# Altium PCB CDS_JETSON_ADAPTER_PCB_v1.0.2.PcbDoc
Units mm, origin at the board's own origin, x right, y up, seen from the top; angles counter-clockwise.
Board outline 70 x 50 mm, 2 copper layers (Top Layer, Bottom Layer); 70 components, 61 nets, 287 pads, 164 vias.
Unrouted connection lines stored in the file: 53.
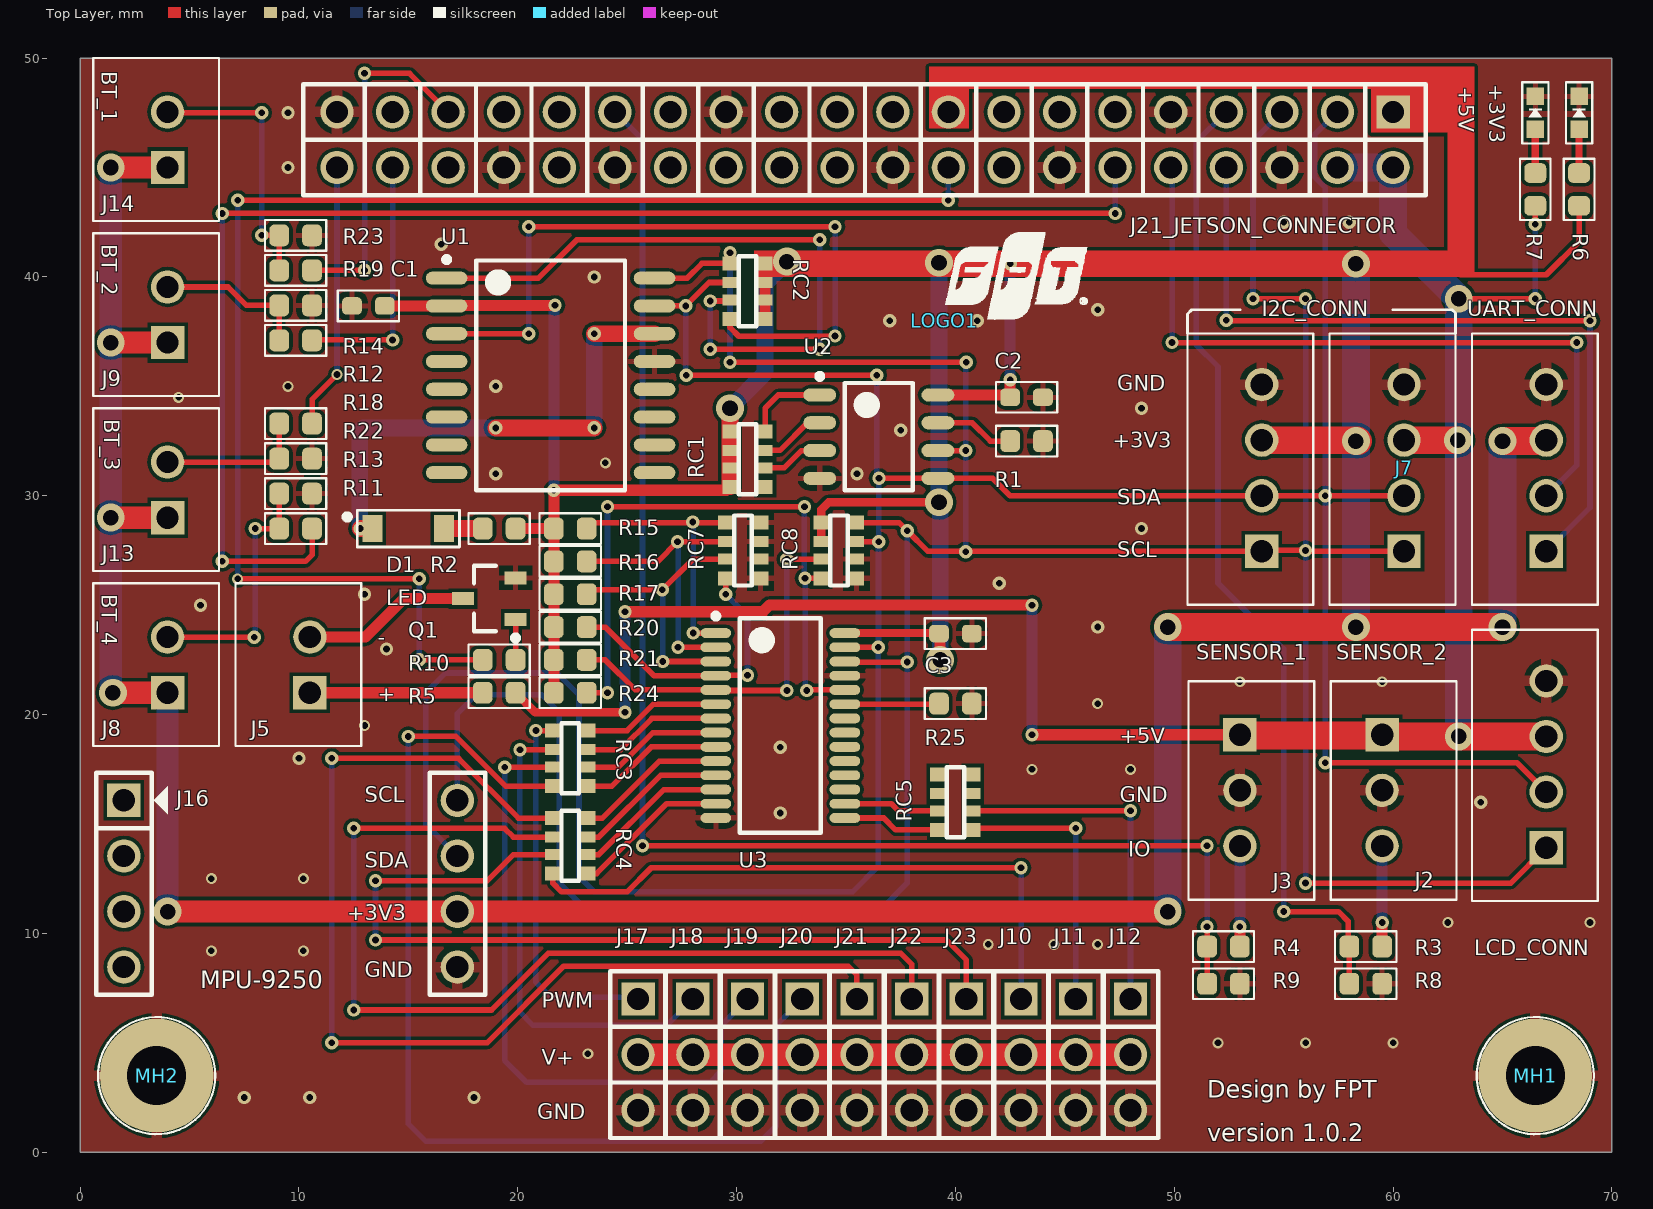
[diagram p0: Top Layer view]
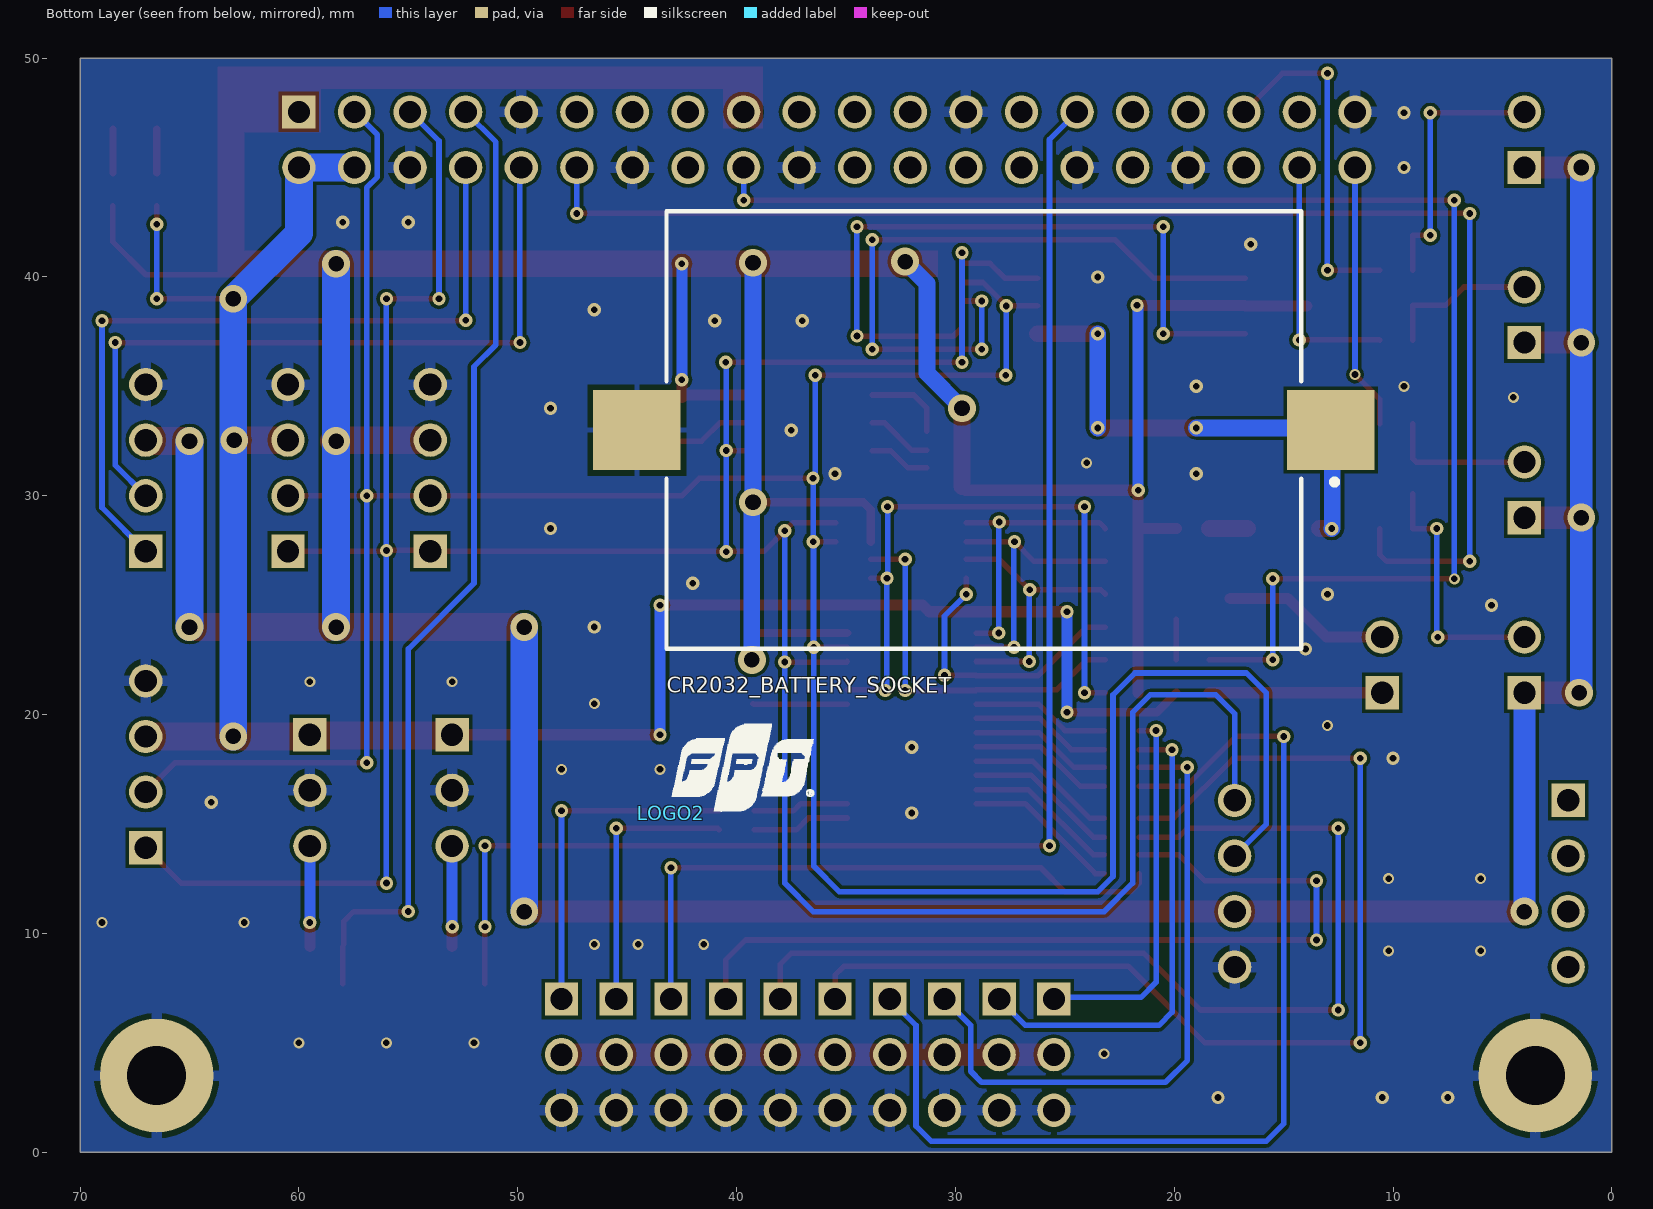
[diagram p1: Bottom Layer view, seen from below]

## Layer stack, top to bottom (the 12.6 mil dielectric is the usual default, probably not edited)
Top Solder: solder mask 0.0102, Solder Resist, Dk 3.5
Top Layer: signal copper 0.0356
Dielectric 1: dielectric 0.32, FR-4, Dk 4.8
Bottom Layer: signal copper 0.0356
Bottom Solder: solder mask 0.0102, Solder Resist, Dk 3.5

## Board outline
0,0 70,0 70,50 0,50

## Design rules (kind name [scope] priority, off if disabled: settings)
Clearance [All] p1: gap=0.152 ignorepadtopadclearanceinfootprint=FALSE
PolygonConnect [All] p1: thpad.connectstyle=Relief thpad.reliefconductorwidth=0.508 thpad.reliefentries=4 thpad.polygonreliefangle="90 Angle" thpad.airgapwidth=0.254 smdpad.connectstyle=Relief smdpad.reliefconductorwidth=0.254 smdpad.reliefentries=4 smdpad.polygonreliefangle="90 Angle" smdpad.airgapwidth=0.254 via.connectstyle=Direct via.reliefconductorwidth=0.254 via.reliefentries=4 via.polygonreliefangle="90 Angle" via.airgapwidth=0.254
RoutingVias [All] p1: holewidth=0.711 width=1.27 viastyle="Through Hole" minholewidth=0.3 minwidth=0.5 maxholewidth=0.711 maxwidth=1.27
SolderMaskExpansion [All] p1: expansion=0.102
Width [All] p1: maxlimit=1.27 minlimit=0.203 preferedwidth=0.254
30 further rules are at their usual default settings.

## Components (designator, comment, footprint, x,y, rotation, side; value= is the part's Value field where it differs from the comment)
+3V3 "LTST-C191KRKT" LED-SMD-0603-RED 68.5,47.5 r270 top (schematic designator LED1)
+5V "LTST-C191KRKT" LED-SMD-0603-RED 66.5,47.5 r270 top (schematic designator LED2)
C1 "GRM188R61A106ME69D" C0603 13.175,38.675 r180 top value=1uF
C2 "GRM188R70J104KA01D" C0603 43.25,34.5 r180 top value=0.1uF
C3 "GRM188R61C106KAALD" C0603 40,23.7 r0 top value=10uF
CR2032_BATTERY_SOCKET "BU2032SM-HD-G" BU2032SM-HD-G 28.7,33 r0 bottom locked (schematic designator BAT1)
D1 "1N4148W-7-F" DO-SOD-123 15,28.5 r0 top
I2C_CONN "HDR_1x4" B4B-XH-A(LF)(SN) 54,27.46 r90 top (schematic designator J4)
J2 "HDR_1x3" B3B-XH-A(LF)(SN) 59.5,16.54 r270 top
J3 "HDR_1x3" B3B-XH-A(LF)(SN) 53,16.54 r270 top
J5 "HDR_1x2" B2B-XH-A(LF)(SN) 10.5,21 r90 top
J7 "HDR_1x4" B4B-XH-A(LF)(SN) 60.5,27.46 r90 top
J8 "HDR_1x2" B2B-XH-A(LF)(SN) 4,21 r90 top
J9 "HDR_1x2" B2B-XH-A(LF)(SN) 4,37 r90 top
J10 "HDR_1x3" PINHEAD_2.54mm_1x3 43,7 r270 top
J11 "HDR_1x3" PINHEAD_2.54mm_1x3 45.5,7 r270 top
J12 "HDR_1x3" PINHEAD_2.54mm_1x3 48,7 r270 top
J13 "HDR_1x2" B2B-XH-A(LF)(SN) 4,29 r90 top
J14 "HDR_1x2" B2B-XH-A(LF)(SN) 4,45 r90 top
J16 "SOCKET_MPU_9250" SOCKET_MPU_9250 2,16.08 r0 top locked
J17 "HDR_1x3" PINHEAD_2.54mm_1x3 25.5,7 r270 top
J18 "HDR_1x3" PINHEAD_2.54mm_1x3 28,7 r270 top
J19 "HDR_1x3" PINHEAD_2.54mm_1x3 30.5,7 r270 top
J20 "HDR_1x3" PINHEAD_2.54mm_1x3 33,7 r270 top
J21 "HDR_1x3" PINHEAD_2.54mm_1x3 35.5,7 r270 top
J21_JETSON_CONNECTOR "HDR_2x20" HEADER_SOCKET_2.54MM_2x20 60,47.54 r180 top (schematic designator J1)
J22 "HDR_1x3" PINHEAD_2.54mm_1x3 38,7 r270 top
J23 "HDR_1x3" PINHEAD_2.54mm_1x3 40.5,7 r270 top
LCD_CONN "HDR_1x4" B4B-XH-A(LF)(SN) 67,13.92 r90 top (schematic designator J15)
LOGO1 "LOGOFPT" LOGO_FPT 39.5,38 r0 top
LOGO2 "LOGOFPT" LOGO_FPT 43,15.5 r180 bottom
MH1 "MTH27" MH_5.2MMD_2.7MMD 66.5,3.5 r0 top locked
MH2 "MTH27" MH_5.2MMD_2.7MMD 3.5,3.5 r0 top locked
Q1 "MMBT3904" MMBT3904 18.7,25.3 r180 top
R1 "RC0603JR-074K7L" R0603 43.25,32.5 r0 top value=4.7K
R2 "RC0603JR-07200RL" R0603 19.15,28.5 r180 top value=200R
R3 "RC0603FR-072K2L" R0603 58.75,9.4 r180 top value=2.2K
R4 "RC0603FR-072K2L" R0603 52.25,9.4 r180 top value=2.2K
R5 "RC0603FR-071KL" R0603 19.15,21 r180 top value=1K
R6 "RC0603FR-071KL" R0603 68.5,44 r90 top value=1K
R7 "RC0603FR-071KL" R0603 66.5,44 r90 top value=1K
R8 "RC0603FR-073K3L" R0603 58.75,7.7 r0 top value=3.3K
R9 "RC0603FR-073K3L" R0603 52.25,7.7 r0 top value=3.3K
R10 "RC0603JR-0710KL" R0603 19.15,22.5 r0 top value=10K
R11 "RC0603FR-07100RL" R0603 9.85,28.5 r0 top value=100R
R12 "RC0603FR-07100RL" R0603 9.85,37.1 r0 top value=100R
R13 "RC0603FR-071KL" R0603 9.85,30.1 r0 top value=1K
R14 "RC0603FR-071KL" R0603 9.85,38.7 r0 top value=1K
R15 "RC0603JR-070RL" R0603 22.4,28.5 r0 top value=0R
R16 "RC0603JR-070RL" R0603 22.4,27 r0 top value=0R
R17 "RC0603JR-070RL" R0603 22.4,25.5 r0 top value=0R
R18 "RC0603FR-07100RL" R0603 9.85,33.3 r0 top value=100R
R19 "RC0603FR-07100RL" R0603 9.85,40.3 r0 top value=100R
R20 "RC0603JR-070RL" R0603 22.4,24 r0 top value=0R
R21 "RC0603JR-070RL" R0603 22.4,22.5 r0 top value=0R
R22 "RC0603FR-071KL" R0603 9.85,31.7 r0 top value=1K
R23 "RC0603FR-071KL" R0603 9.85,41.9 r0 top value=1K
R24 "RC0603JR-070RL" R0603 22.4,21 r0 top value=0R
R25 "RC0603JR-0710KL" R0603 40,20.5 r0 top value=10K
RC1 "YC164-JR-074K7L" RC_1206 30.5,31.675 r90 top value=4.7K
RC2 "YC164-JR-074K7L" RC_1206 30.5,39.345 r270 top value=4.7K
RC3 "YC164-JR-07220RL" RC_1206 22.4,18 r270 top value=220R
RC4 "YC164-JR-07220RL" RC_1206 22.4,14 r270 top value=220R
RC5 "YC164-JR-07220RL" RC_1206 40,16 r90 top value=220R
RC7 "YC164-JR-0710KL" RC_1206 30.3,27.5 r90 top value=10K
RC8 "YC164-JR-0710KL" RC_1206 34.673,27.5 r90 top value=10K
U1 "DS3231S#T&R" SOIC127P1030X265-16N 21.5,35.5 r0 top
U2 "CAT24C32WI-GT3" SOIC127P600X175-8N 36.5,32.7 r0 top
U3 "PCA9685PW" TSOP65P640X110-28N 32,19.5 r0 top
UART_CONN "HDR_1x4" B4B-XH-A(LF)(SN) 67,27.46 r90 top (schematic designator J6)

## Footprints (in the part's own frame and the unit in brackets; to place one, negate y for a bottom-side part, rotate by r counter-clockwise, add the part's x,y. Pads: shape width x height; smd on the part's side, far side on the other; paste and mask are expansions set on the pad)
B2B-XH-A(LF)(SN) [mil] "CONN HEADER XH TOP 2POS 2.5MM"
  rect 60x60 hole 40: 1(0,0)
  round 60 hole 40: 2(100,0)
  silkscreen extent -96,-93 197,134, body extent -96,-93 195,134, height 276
B3B-XH-A(LF)(SN) [mil]
  rect 60x60 hole 40: 1(-100,0)
  round 60 hole 40: 2(0,0) 3(100,0)
  silkscreen extent -196,-93 197,134, body extent -195,-93 195,133, height 276
B4B-XH-A(LF)(SN) [mil]
  rect 60x60 hole 40: 1(0,0)
  round 60 hole 40: 2(100,0) 3(200,0) 4(300,0)
  silkscreen extent -96,-93 392,134, body extent -96,-93 392,134, height 276
BU2032SM-HD-G [mm] "SODFL, 2-Leads, Body 20.00x32.00mm, IPC Medium Density"
  rect 4x3.65 smd: 1(-15.858,0) 2(15.858,0)
  silkscreen extent -16.15,-10 14.5,10, body extent -16,-10 16,10, height 5.3
C0603 [mm]
  rrect50% 0.9x0.8 smd: 1(-0.75,0) 2(0.75,0)
  silkscreen extent -1.4,-0.7 1.4,0.7, body extent -0.8,-0.4 0.8,0.41, height 0.87
DO-SOD-123 [mil]
  rect 36x48 smd: 1(-64.5,0) 2(64.5,0)
  silkscreen extent -115,-33 92,33, body extent -76,-27 76,27, height 32
HEADER_SOCKET_2.54MM_2x20 [mil]
  rect 60x60 hole 40: 1(0,0)
  round 60 hole 40: 2(0,100) 3(100,0) 4(100,100) 5(200,0) 6(200,100) 7(300,0) 8(300,100) 9(400,0) 10(400,100) 11(500,0) 12(500,100) 13(600,0) 14(600,100) 15(700,0) 16(700,100) 17(800,0) 18(800,100) 19(900,0) 20(900,100) 21(1000,0) 22(1000,100) 23(1100,0) 24(1100,100) 25(1200,0) 26(1200,100) 27(1300,0) 28(1300,100) 29(1400,0) 30(1400,100) 31(1500,0) 32(1500,100) 33(1600,0) 34(1600,100) 35(1700,0) 36(1700,100) 37(1800,0) 38(1800,100) 39(1900,0) 40(1900,100)
  silkscreen extent -59,-50 1961,150, body extent -60,-47 1960,147, height 372
LED-SMD-0603-RED [mm] "Chip Diode, 2-Leads, Body 1.60x0.80mm, IPC Medium Density"
  rect 0.8x0.8 smd: A(0.75,0) C(-0.75,0)
  silkscreen extent -1.4,-0.6 1.4,0.6, body extent -0.8,-0.4 0.8,0.4, height 0.6
LOGO_FPT [mm]
  silkscreen extent 0.04,0.06 6.54,4.05
MH_5.2MMD_2.7MMD [mm]
  round 5.2 / inner round 3.683 / far side round 5.2 hole 2.7: 1(0,0)
  silkscreen extent -2.68,-2.68 2.68,2.68
MMBT3904 [mm] "SOT23, 3-Leads, Body 2.92x2.37mm, Pitch 0.95mm, IPC Medium Density"
  rect 1x0.6 smd: 1(-1.2,0.95) 2(-1.2,-0.95) 3(1.2,0)
  silkscreen extent -1.33,-1.5 0.7,1.92, body extent -1.5,-1.5 1.5,1.5, height 1.3
PINHEAD_2.54mm_1x3 [mil]
  rect 60x60 hole 40: 1(0,0)
  round 60 hole 40: 2(100,0) 3(200,0)
  silkscreen extent -50,-50 250,50, body extent -53,-53 253,53, height 340
R0603 [mm]
  rrect50% 0.9x1 smd: 1(-0.75,0) 2(0.75,0)
  silkscreen extent -1.4,-0.7 1.4,0.7, body extent -0.8,-0.4 0.8,0.4, height 0.45
RC_1206 [mm] "Chip Resistor Array 47R - 221 KR"
  rect 0.64x0.7 smd: 1(-1.27,-0.8) 4(1.27,-0.8) 5(1.27,0.8) 8(-1.27,0.8)
  rect 0.5x0.7 smd: 2(-0.4,-0.8) 3(0.4,-0.8) 6(0.4,0.8) 7(-0.4,0.8)
  silkscreen extent -1.6,-0.4 1.6,0.4, body extent -1.68,-0.88 1.68,0.88, height 0.71
SOCKET_MPU_9250 [mil]
  rect 60x60 hole 40: 1(0,0)
  round 60 hole 40: 2(0,-100) 3(0,-200) 4(0,-300) 5(600,-300) 6(600,-200) 7(600,-100) 8(600,0)
  silkscreen extent -50,-350 650,50, body extent -54,-590 652,79, height 575
SOIC127P600X175-8N [mm] "SOIC, 8-Leads, Body 4.90x3.90mm, Pitch 1.27mm, IPC Medium Density"
  oval 1.5x0.6 smd: 1(-2.7,1.905) 2(-2.7,0.635) 3(-2.7,-0.635) 4(-2.7,-1.905) 5(2.7,-1.905) 6(2.7,-0.635) 7(2.7,0.635) 8(2.7,1.905)
  silkscreen extent -2.82,-2.45 1.55,2.88, body extent -3,-2.45 3,2.45, height 1.75
SOIC127P1030X265-16N [mm] "SOIC, 16-Leads, Body 10.30x7.50mm, Pitch 1.27mm, IPC Medium Density"
  oval 1.9x0.6 smd: 1(-4.75,4.445) 2(-4.75,3.175) 3(-4.75,1.905) 4(-4.75,0.635) 5(-4.75,-0.635) 6(-4.75,-1.905) 7(-4.75,-3.175) 8(-4.75,-4.445) 9(4.75,-4.445) 10(4.75,-3.175) 11(4.75,-1.905) 12(4.75,-0.635) 13(4.75,0.635) 14(4.75,1.905) 15(4.75,3.175) 16(4.75,4.445)
  silkscreen extent -4.87,-5.25 3.4,5.42, body extent -5.15,-5.25 5.15,5.25, height 2.65
TSOP65P640X110-28N [mm] "TSOP, 28-Leads, Body 9.70x4.40mm, Pitch 0.65mm, IPC Medium Density"
  oval 1.4x0.45 smd: 1(-2.95,4.225) 2(-2.95,3.575) 3(-2.95,2.925) 4(-2.95,2.275) 5(-2.95,1.625) 6(-2.95,0.975) 7(-2.95,0.325) 8(-2.95,-0.325) 9(-2.95,-0.975) 10(-2.95,-1.625) 11(-2.95,-2.275) 12(-2.95,-2.925) 13(-2.95,-3.575) 14(-2.95,-4.225) 15(2.95,-4.225) 16(2.95,-3.575) 17(2.95,-2.925) 18(2.95,-2.275) 19(2.95,-1.625) 20(2.95,-0.975) 21(2.95,-0.325) 22(2.95,0.325) 23(2.95,0.975) 24(2.95,1.625) 25(2.95,2.275) 26(2.95,2.925) 27(2.95,3.575) 28(2.95,4.225)
  silkscreen extent -3.07,-4.9 1.85,5.12, body extent -3.2,-4.9 3.2,4.9, height 1.1

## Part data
+3V3 +5V: "LED RED CLEAR 0603 SMD", Current - Test=20mA, Led Color=Red, Lens Color=Colorless, Manufacturer Name="Lite-One Inc.", Millicandela Rating=54mcd, Package="0603 (1608 Metric)", Part Name=LED-SMD-1608-55, Voltage - Forward (Vf) (Typ)=2V
C1: "CAP CER 10UF 10V X5R 0603", Manufacturer Name=Murata, Operating Temperature="-55°C ~ 85°C", Package="0603 (1608 Metric)", Part Name=CAP-CERAMIC-0603, Rated Voltage=10V, Tolerance=±20%
C2: "CAP CER 0.1UF 6.3V X7R 0603", Manufacturer Name=Murata, Operating Temperature="-55°C ~ 125°C", Package="0603 (1608 Metric)", Part Name=CAP-CERAMIC-0603, Rated Voltage=6.3V, Tolerance=10%
C3: "CAP CER 10UF 16V X5R 0603", Manufacturer Name=Murata, Operating Temperature="-55°C ~ 125°C", Package="0603 (1608 Metric)", Part Name=CAP-CERAMIC-0603, Rated Voltage=16V, Tolerance=±10%
CR2032_BATTERY_SOCKET: "=Description", Manufacturer Name=MPD, Manufacturer Part Description="HOLDER COIN CELL 2032 SMD", Operating Temperature="-40°C ~ 280°C", Part Name="Battery Holder"
D1: "DIODE GEN PURP 100V 300MA SOD123", Capacitance="2pF @ 0V, 1MHz", Current Average Rectified (Io)="300mA (DC)", Current Reverse Leakage @ Vr="1µA @ 75V", Manufacturer Name="Diodes Incorporated", Operating Temperature="-55°C ~ 150°C (TJ)", Voltage DC Reverse (Vr) (Max)=100V, Voltage Forward (Vf) (Max)="1.25V @ 150mA"
I2C_CONN J7 LCD_CONN UART_CONN: library part B4B-XH-A(LF)(SN), "CONN HEADER XH TOP 4POS 2.5MM", Manufacturer Name="JST Sales America Inc.", Supplier Part Number=Digi-Key
J2 J3: library part B3B-XH-A(LF)(SN)
J5 J8 J9 J13 J14: library part B2B-XH-A(LF)(SN), "CONN HEADER XH TOP 2POS 2.5MM", Manufacturer Name="JST Sales America Inc", Supplier Part Number=Digi-Key
J10 J11 J12 J17 J18 J19 J20 J21 J22 J23: library part 61300311121, "CONN HEADER 3 POS 2.54", Manufacturer Name="Wurth Electronics Inc.", Supplier Part Number=Digi-Key
J16: library part MPU_9250
J21_JETSON_CONNECTOR: library part SSW-120-03-G-D, "CONN RCPT .100\" 40POS DUAL GOLD", Manufacturer Name="Samtec Inc.", Part Name=HEADER_SOCKET_2.54MM_2x20, Supplier Part Number=Digi-Key
LOGO1 LOGO2: library part LOGO-FPT, "=Description", Manufacturer Part Description="FPT Logo", Part Name=LOGO
MH1 MH2: "=Description", Manufacturer Part Description="Mouting Hole 2.7mm"
Q1: "TRANS NPN 40V 0.2A SOT23", Frequency - Transition=350mW, Manufacturer Name="Fairchild/ON Semiconductor", Operating Temperature="-55°C ~ 150°C (TJ)", Package=SOT-23-3, Part Name=TRANS-NPN, Supplier Part Number 1=MMBT3904FSDKR-ND, Voltage - Collector Emitter Breakdown (Max)=40V
R1: "RES SMD 4.7K OHM 5% 1/10W 0603", Manufacturer Name=Yageo, Operating Temperature="-55°C ~ 155°C", Package=0603, Part Name=RES-0603, Rated Power=0.1W, Tolerance=±5%
R2: "RES SMD 200 OHM 5% 1/10W 0603", Manufacturer Name=Yageo, Operating Temperature="-55°C ~ 155°C", Package=0603, Part Name=RES-0603, Rated Power=0.1W, Tolerance=±5%
R3 R4: "RES SMD 2.2K OHM 1% 1/10W 0603", Manufacturer Name=Yageo, Operating Temperature="-55°C ~ 155°C", Package=0603, Part Name=RES-0603, Rated Power=0.063W, Tolerance=1%
R5 R6 R7 R13 R14 R22 R23: "RES SMD 1K OHM 1% 1/10W 0603", Manufacturer Name=Yageo, Operating Temperature="-55°C ~ 155°C", Package=0603, Part Name=RES-0603, Rated Power=0.15W, Tolerance=1%
R8 R9: "RES SMD 3.3K OHM 1% 1/10W 0603", Manufacturer Name=Yageo, Operating Temperature="-55°C ~ 155°C", Package=0603, Part Name=RES-0603, Rated Power=0.1W, Tolerance=±1%
R10 R25: "RES SMD 10K OHM 5% 1/10W 0603", Manufacturer Name=Yageo, Operating Temperature="-55°C ~ 155°C", Package=0603, Part Name=RES-0603, Rated Power=0.1W, Tolerance=±5%
R11 R12 R18 R19: "RES SMD 100 OHM 1% 1/10W 0603", Manufacturer Name=Yageo, Operating Temperature="-55°C ~ 155°C", Package=0603, Part Name=RES-0603, Rated Power=0.15W, Tolerance=1%
R15 R16 R17 R20 R21 R24: "RES SMD 0.0OHM JUMPER 1/10W 0603", Manufacturer Name=Yageo, Operating Temperature="-55°C ~ 155°C", Package=0603, Part Name=RES-0603, Rated Power=0.15W, Tolerance=1%
RC1 RC2: "RES ARRAY 4 RES 4.7K OHM 1206", Manufacturer Name=Yageo, Operating Temperature="-55°C ~ 155°C", Package=1206, Part Name=RC, Rated Power=0.1W, Tolerance=±5%
RC3 RC4 RC5: "RES ARRAY 4 RES 220 OHM 1206", Manufacturer Name=Yageo, Operating Temperature="-55°C ~ 155°C", Package=1206, Part Name=RC, Rated Power=0.1W, Tolerance=±5%
RC7 RC8: "RES ARRAY 4 RES 10K OHM 1206", Manufacturer Name=Yageo, Operating Temperature="-55°C ~ 155°C", Package=1206, Part Name=RC, Rated Power=0.1W, Tolerance=±5%
U1: "IC RTC CLK/CALENDAR I2C 16-SOIC", Current - Timekeeping (Max)="110µA ~ 170µA @ 3.63V ~ 5.5V", Manufacturer Name=Maxim, Operating Temperature="0°C ~ 70°C", Voltage - Supply="2.3 V ~ 5.5 V"
U2: "IC EEPROM 32K I2C 1MHZ 8SOIC", Manufacturer Name="ON Semiconductor", Operating Temperature="-40°C ~ 85°C (TA)", Package=8-SOIC, Voltage Supply="1.7 V ~ 5.5 V"
U3: "IC LED DRIVER RGBA 28-TSSOP", Current - Output / Channel=25mA, Frequency=-, Manufacturer Name="NXP USA Inc.", Manufacturer Part Number=PCA9685PW,118, Operating Temperature="-40°C ~ 85°C (TA)", Voltage - Output=5.5V, Voltage - Supply (Min)=2.3V

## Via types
v1: diameter 0.61, hole 0.305, Top Layer to Bottom Layer, tented both sides, 120 vias
v2: diameter 0.5, hole 0.3, Top Layer to Bottom Layer, tented both sides, 24 vias
v3: diameter 1.27, hole 0.711, Top Layer to Bottom Layer, tented both sides, 20 vias

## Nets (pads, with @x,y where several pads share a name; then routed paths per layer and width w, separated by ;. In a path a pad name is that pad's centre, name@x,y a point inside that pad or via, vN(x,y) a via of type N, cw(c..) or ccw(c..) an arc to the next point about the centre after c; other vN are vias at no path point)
32K: RC2.3 U1.1 | length 30.9
  Top Layer w0.254: U1.1 20.945,39.945 22.7,41.7 v1(33.8,41.7) ; v1(28.8,36.7) v1(33.8,36.7) ; v1(28.8,38.9) 29.655,38.9 RC2.3
  Bottom Layer w0.254: v1(28.8,36.7) v1(28.8,38.9) ; v1(33.8,36.7) v1(33.8,41.7)
+3V3_VDC: C1.1 C2.2 C3.1 I2C_CONN.3 J8.1 J9.1 J13.1 J14.1 J16.6 J21_JETSON_CONNECTOR.1 J21_JETSON_CONNECTOR.17 R2.1 R6.1 R15.1 R16.1 R17.1 R20.1 R21.1 R24.1 RC1.5 RC1.6 RC1.7 RC1.8 RC2.5 RC2.6 RC2.7 RC2.8 RC8.5 RC8.6 U1.2 U2.8 U3.28 UART_CONN.3 | length 247.2
  Top Layer w0.254: 63.1,40.1 67,40.1 68.5,41.6 R6.1
  Top Layer w0.381: RC8.6 RC8.5 33.873,29.373 34.2,29.7 v3(39.25,29.7) v3@39.3,29.7 ; U3.28 C3.1@39.225,23.725
  Top Layer w0.508: C1.1 U1.2 16.775,38.7 v1(21.7,38.7) ; R2.1 R15.1 ; R24.1 R21.1 R20.1 R17.1 R16.1 R15.1 ; RC1.8 29.545,30.25 v1(21.65,30.25) R15.1 ; RC2.5 RC2.6 RC2.7 RC2.8 ; U2.8 42.395,34.605 C2.2 v1(42.5,35.3) ; C3.1@39.225,23.725 C3.1 39.2,23.65 39.3,23.55 v3(39.3,22.5) ; v3(58.3,40.6) v3@58.3,40.7
  Top Layer w0.762: RC1.8 RC1.5 v3(29.7,34)
  Top Layer w1.016: v3(1.4,29) J13.1 ; v3(1.4,37) J9.1 ; v3(1.4,45) J14.1 ; v3(1.5,21) J8.1 ; v3(4,11) J16.6 v3(49.7,11)
  Top Layer w1.27: v3(49.7,24) v3(58.3,24) v3(65,24) ; I2C_CONN.3 58.36,32.54 58.4,32.5 v3(58.3,32.5) ; v3(65,32.5) 66.96,32.5 UART_CONN.3
  Bottom Layer w0.508: v1(21.65,30.25) v1@21.65,38.65 ; v1(42.5,35.3) v1(42.5,40.6)
  Bottom Layer w0.762: v3(29.7,34) 31.3,35.6 31.3,39.7 v3(32.3,40.7) ; v3(39.25,40.65) v3(39.25,29.7) 39.3,29.65 v3(39.3,22.5)
  Bottom Layer w1.016: v3(1.4,45) v3(1.4,37) v3(1.4,29) 1.4,21.1 v3(1.5,21) ; v3(4,11) J8.1
  Bottom Layer w1.27: v3(49.7,11) v3(49.7,24) ; v3(58.3,24) v3(58.3,32.5) v3(58.3,40.6) ; v3(65,24) v3(65,32.5)
+5V_VDC: J2.1 J3.1 J7.3 J21_JETSON_CONNECTOR.2 J21_JETSON_CONNECTOR.4 LCD_CONN.3 R5.1 R7.1 | length 98.3
  Top Layer w0.254: v3(63,39) v1(66.5,39) ; v1(66.5,42.4) R7.1
  Top Layer w0.381: R5.1 20.8,20.1 v1(24.9,20.1)
  Top Layer w0.508: v1(24.9,24.7) 31.2,24.7 31.5,25 v1(43.5,25) ; v1(43.5,19.08) J3.1
  Top Layer w1.27: J3.1@52.95,19.04 59.41,19.04 J2.1@59.45,19.08 ; J2.1@59.53,19 v3(63,19) LCD_CONN.3 ; J7.3 v3(62.96,32.54)
  Bottom Layer w0.254: v1(66.5,39) v1(66.5,42.4)
  Bottom Layer w0.508: v1(24.9,20.1) v1(24.9,24.7) ; v1(43.5,19.08) v1(43.5,25)
  Bottom Layer w1.27: J21_JETSON_CONNECTOR.4 J21_JETSON_CONNECTOR.2 60,42 v3(63,39) v3@63,32.5 ; J2.1@59.45,19.08 J2.1@59.53,19 ; v3(62.96,32.54) v3@63,32.5 ; v3(63,19) v3@63,32.5
\O\E\: R25.1 U3.23 | length 4.3
  Top Layer w0.254: U3.23 39.225,20.475 R25.1
A0: R15.2 RC7.5 U3.1 | length 12.6
  Top Layer w0.254: R15.2 23.42,28.77 RC7.5 ; v1(28.025,23.725) U3.1
  Bottom Layer w0.254: v1(28,28.8) 28.025,28.775 v1(28.025,23.725)
A1: R16.2 RC7.6 U3.2 | length 13.1
  Top Layer w0.254: R16.2 26.4,27 v1(27.3,27.9) ; v1(27.325,23.075) U3.2 ; v1@27.5,27.9 RC7.6
  Bottom Layer w0.254: v1(27.3,27.9) 27.325,27.875 v1(27.325,23.075)
A2: R17.2 RC7.7 U3.3 | length 12.7
  Top Layer w0.254: R17.2 23.35,25.7 v1(26.6,25.7) 28,27.1 RC7.7 ; v1(26.625,22.425) U3.3
  Bottom Layer w0.254: v1(26.6,25.7) 26.625,25.675 v1(26.625,22.425)
A3: R20.2 RC7.8 U3.4 | length 13.1
  Top Layer w0.254: R20.2 24,24 26.225,21.775 U3.4 29.075,21.8 v1(30.5,21.8) ; v1(29.5,25.5) RC7.8
  Bottom Layer w0.254: v1(29.5,25.5) 30.5,24.5 v1(30.5,21.8)
A4: R21.2 RC8.7 U3.5 | length 17.3
  Top Layer w0.254: R21.2 24,22.5 25.375,21.125 U3.5 29.075,21.1 v1(32.3,21.1) ; v1(32.3,27.1) RC8.7
  Bottom Layer w0.254: v1(32.3,21.1) v1(32.3,27.1)
A5: R24.2 RC8.8 U3.24 | length 29.3
  Top Layer w0.254: R24.2 v1(24.1,21) ; v1(24.1,29.5) v1(33.1,29.5) ; v1(33.13,26.23) RC8.8 ; v1(33.2,21.1) 33.225,21.125 U3.24
  Bottom Layer w0.254: v1(24.1,21) v1(24.1,29.5) ; v1(33.1,29.5) 33.1,26.26 v1(33.13,26.23) v1@33.13,21.13
ANODE: J5.1 R5.2 | length 7.9
  Top Layer w0.508: J5.1 R5.2
BAT: CR2032_BATTERY_SOCKET.1 D1.1 U1.14 | length 22.9
  Top Layer w0.762: v1(12.8,28.5) D1.1 ; v1(19,33.1) v1(23.5,33.1) ; v1(23.5,37.4) 23.505,37.405 U1.14
  Bottom Layer w0.762: v1(12.8,28.5) 12.784,28.516 12.784,33 CR2032_BATTERY_SOCKET.1 12.942,33.1 v1(19,33.1) ; v1(23.5,33.1) v1(23.5,37.4)
CATHODE: J5.2 Q1.3 | length 7.7
  Top Layer w0.508: J5.2 13.04,23.54 14.8,25.3 Q1.3@17.45,25.3
GND: +3V3.C +5V.C C1.2 C2.1 C3.2 CR2032_BATTERY_SOCKET.2 I2C_CONN.4 J2.2 J3.2 J7.4 J10.3 J11.3 J12.3 J16.5 J17.3 J18.3 J19.3 J20.3 J21.3 J21_JETSON_CONNECTOR.6 J21_JETSON_CONNECTOR.9 J21_JETSON_CONNECTOR.14 J21_JETSON_CONNECTOR.20 J21_JETSON_CONNECTOR.25 J21_JETSON_CONNECTOR.30 J21_JETSON_CONNECTOR.34 J21_JETSON_CONNECTOR.39 J22.3 J23.3 LCD_CONN.4 MH1.1 MH2.1 Q1.2 R1.2 R8.2 R9.2 R13.2 R14.2 R22.2 R23.2 R25.2 RC7.1 RC7.2 RC7.3 RC7.4 RC8.1 RC8.2 U1.13 U2.4 U3.14 U3.25 UART_CONN.4
  other v1: 7.5,2.5 10.5,2.5 18,2.5 32,15.5 64,16 10,18 32,18.5 14,23 46.5,24 5.5,25 13,25.5 42,26 48.5,28.5 19,31 35.5,31 37.5,33 48.5,34 19,35 37,38 41,38 46.5,38.5 23.5,40 16.5,41.5 55,42.5 58,42.5 9.5,45 9.5,47.5
  other v2: 23.2,4.5 52,5 56,5 60,5 6,9.2 10.2,9.2 41.5,9.5 44.5,9.5 46.5,9.5 62.5,10.5 69,10.5 6,12.5 10.2,12.5 43.5,17.5 48,17.5 13,19.5 46.5,20.5 53,21.5 59.5,21.5 24,31.5 4.5,34.5 9.5,35
GPIO_392: J21_JETSON_CONNECTOR.12 R11.2 | length 64.2
  Top Layer w0.254: v1(6.5,27) 10.3,27 10.6,27.3 R11.2 ; v1(6.5,42.9) v1(47.3,42.9)
  Bottom Layer w0.254: v1(6.5,27) v1(6.5,42.9) ; v1(47.3,42.9) J21_JETSON_CONNECTOR.12
GPIO_393: J21_JETSON_CONNECTOR.40 R18.2 | length 12.2
  Top Layer w0.254: R18.2 10.6,34.4 v2(11.74,35.54)
  Bottom Layer w0.254: v2(11.74,35.54) J21_JETSON_CONNECTOR.40
GPIO_394: J21_JETSON_CONNECTOR.38 R12.2 | length 11.6
  Top Layer w0.254: R12.2 10.62,37.12 v1(14.28,37.12)
  Bottom Layer w0.254: v1(14.28,37.12) J21_JETSON_CONNECTOR.38
GPIO_395: J21_JETSON_CONNECTOR.35 R19.2 | length 15.9
  Top Layer w0.254: R19.2 v1(13,40.3) ; v1(13,49.3) 15.06,49.3 J21_JETSON_CONNECTOR.35
  Bottom Layer w0.254: v1(13,40.3) v1(13,49.3)
GPIO_396: J21_JETSON_CONNECTOR.7 R3.2 R8.1 | length 44.7
  Top Layer w0.254: v1(55,11) 57.5,11 57.95,10.55 R3.2@57.95,9.5 ; R8.1 R3.2
  Bottom Layer w0.254: J21_JETSON_CONNECTOR.7 51,46.16 51,36.9 52,35.9 52,26 55,23 v1(55,11)
GPIO_398: J21_JETSON_CONNECTOR.29 R4.2 R9.1 | length 66.2
  Top Layer w0.254: v1@25.74,13.96 v1(25.7,14) v1(51.5,14) ; R9.1 R4.2 v1(51.5,10.3)
  Bottom Layer w0.254: J21_JETSON_CONNECTOR.29 25.7,46.28 v1(25.7,14) ; v1(51.5,10.3) v1(51.5,14)
GPIO_481: J21_JETSON_CONNECTOR.18 R10.1 | length 66.2
  Top Layer w0.254: v2(7.2,26.2) v1(15.5,26.2) ; v1(7.2,43.5) v1(39.68,43.5) ; v1(15.5,22.5) R10.1
  Bottom Layer w0.254: v2(7.2,26.2) v1(7.2,43.5) ; v1(15.5,22.5) v1(15.5,26.2) ; v1(39.68,43.5) J21_JETSON_CONNECTOR.18
LED_0: RC3.8 U3.6 | length 6.3
  Top Layer w0.254: RC3.8 24.996,19.27 26.201,20.475 U3.6
LED_1: RC3.7 U3.7 | length 6.4
  Top Layer w0.254: RC3.7 24.701,18.4 26.126,19.825 U3.7
LED_2: RC3.6 U3.8 | length 6.5
  Top Layer w0.254: RC3.6 24.6,17.6 26.175,19.175 U3.8
LED_3: RC3.5 U3.9 | length 6.6
  Top Layer w0.254: RC3.5 24.305,16.73 26.1,18.525 U3.9
LED_4: RC4.8 U3.10 | length 6.9
  Top Layer w0.254: RC4.8 23.87,15.27 26.475,17.875 U3.10
LED_5: RC4.7 U3.11 | length 7
  Top Layer w0.254: RC4.7 23.7,14.4 26.525,17.225 U3.11
LED_6: RC4.6 U3.12 | length 7.1
  Top Layer w0.254: RC4.6 23.7,13.6 26.675,16.575 U3.12
LED_7: RC4.5 U3.13 | length 7.2
  Top Layer w0.254: RC4.5 23.604,12.73 26.799,15.925 U3.13
LED_8: RC5.8 U3.15 | length 4.5
  Top Layer w0.254: U3.15 36.725,15.275 37.27,14.73 RC5.8
LED_9: RC5.7 U3.16 | length 4.4
  Top Layer w0.254: U3.16 37.075,15.925 37.4,15.6 RC5.7
NetD1_2: D1.2 R2.2 | length 1.8
  Top Layer w0.762: D1.2 R2.2
NetJ2_3: J2.3 R3.1 | length 4.6
  Top Layer w0.508: R3.1 v1(59.5,10.5)
  Bottom Layer w0.508: v1(59.5,10.5) J2.3
NetJ3_3: J3.3 R4.1 | length 4.6
  Top Layer w0.508: R4.1 v1(53,10.3)
  Bottom Layer w0.508: v1(53,10.3) J3.3
NetJ8_2: J8.2 R11.1 R13.1 | length 11.6
  Top Layer w0.254: J8.2 v1(7.96,23.54) ; v1(8,28.5) R11.1 R13.1
  Bottom Layer w0.254: v1(7.96,23.54) 8,23.58 v1(8,28.5)
NetJ9_2: J9.2 R12.1 R14.1 | length 7
  Top Layer w0.254: J9.2 6.76,39.54 7.6,38.7 R14.1 R12.1
NetJ13_2: J13.2 R18.1 R22.1 | length 6.8
  Top Layer w0.254: J13.2 8.94,31.54 R22.1 R18.1
NetJ14_2: J14.2 R19.1 R23.1 | length 12.3
  Top Layer w0.254: J14.2 4.04,47.5 v1(8.3,47.5) ; v1(8.3,41.9) R23.1 R19.1
  Bottom Layer w0.254: v1(8.3,41.9) v1(8.3,47.5)
NetLED1_A: +3V3.A R6.2 | length 2
  Top Layer w0.33: R6.2 +3V3.A
NetLED2_A: +5V.A R7.2 | length 2
  Top Layer w0.33: R7.2 +5V.A
NetQ1_1: Q1.1 R10.2 | length 1.9
  Top Layer w0.254: R10.2 Q1.1
NetR1_1: R1.1 U2.7 | length 3.6
  Top Layer w0.254: U2.7 40.765,33.335 41.6,32.5 R1.1
NetRC1_2: RC1.2 U2.3 | length 2.8
  Top Layer w0.254: RC1.2 32.175,31.275 32.965,32.065 U2.3
NetRC1_3: RC1.3 U2.2 | length 3
  Top Layer w0.254: RC1.3 31.975,32.075 33.235,33.335 U2.2
NetRC1_4: RC1.4 U2.1 | length 3.8
  Top Layer w0.254: RC1.4 31.3,34 31.905,34.605 U2.1
PWM_0: J17.1 RC3.1 | length 17.1
  Top Layer w0.254: v1(20.83,19.27) RC3.1
  Bottom Layer w0.254: v1(20.83,19.27) 20.83,7.77 21.52,7.08 25.42,7.08 J17.1@25.423,7.077
PWM_1: J18.1 RC3.2 | length 22.1
  Top Layer w0.254: v1(20.1,18.4) RC3.2
  Bottom Layer w0.254: v1(20.1,18.4) 20.1,6.4 20.7,5.8 26.8,5.8 J18.1
PWM_2: J19.1 RC3.3 | length 29.9
  Top Layer w0.254: v1(19.4,17.6) RC3.3
  Bottom Layer w0.254: v1(19.4,17.6) 19.4,4.2 20.4,3.2 28.8,3.2 29.3,3.7 29.3,5.8 J19.1
PWM_3: J20.1 RC3.4 | length 49
  Top Layer w0.254: v1(15,19) 17.174,19 19.444,16.73 RC3.4
  Bottom Layer w0.254: v1(15,19) 15,1.3 15.8,0.5 31.1,0.5 31.8,1.2 31.8,5.8 J20.1
PWM_4: J21.1 RC4.1 | length 50.9
  Top Layer w0.254: v1(11.5,5) 18.6,5 22.1,8.5 35.1,8.5 35.5,8.1 J21.1 ; v1(11.5,18) 17.3,18 20.03,15.27 RC4.1
  Bottom Layer w0.254: v1(11.5,5) v1(11.5,18)
PWM_5: J22.1 RC4.2 | length 45.9
  Top Layer w0.254: v1(12.5,6.5) 18.8,6.5 21.4,9.1 37.5,9.1 38,8.6 J22.1 ; v1(12.5,14.8) 19.4,14.8 19.8,14.4 RC4.2
  Bottom Layer w0.254: v1(12.5,6.5) v1(12.5,14.8)
PWM_6: J23.1 RC4.3 | length 40.5
  Top Layer w0.254: v1(13.5,9.7) 39.584,9.7 40.5,8.784 J23.1 ; v1(13.5,12.4) 18.6,12.4 19.8,13.6 RC4.3
  Bottom Layer w0.254: v1(13.5,9.7) v1(13.5,12.4)
PWM_7: J10.1 RC4.4 | length 28.5
  Top Layer w0.254: RC4.4 21.6,12.3 22,11.9 25,11.9 26.1,13 v1(43,13)
  Bottom Layer w0.254: J10.1 v1(43,13)
PWM_8: J11.1 RC5.1 | length 12.5
  Top Layer w0.254: RC5.1 40.87,14.8 v1(45.5,14.8)
  Bottom Layer w0.254: J11.1 v1(45.5,14.8)
PWM_9: J12.1 RC5.2 | length 15.8
  Top Layer w0.254: RC5.2 v1(48,15.6)
  Bottom Layer w0.254: J12.1 v1(48,15.6)
RXD0: J21_JETSON_CONNECTOR.10 UART_CONN.2 | length 34.1
  Top Layer w0.254: v1(49.9,37) v1(68.4,37)
  Bottom Layer w0.254: J21_JETSON_CONNECTOR.10 49.9,44.94 v1(49.9,37) ; UART_CONN.2 68.4,31.4 v1(68.4,37)
SCL: I2C_CONN.1 J7.1 J16.8 J21_JETSON_CONNECTOR.5 LCD_CONN.1 RC2.1 RC8.4 U1.16 U2.6 U3.26 | length 158.4
  Top Layer w0.254: U1.16 27.745,39.945 28.415,40.615 RC2.1 v1(29.7,41.1) ; v1(29.7,36.1) v1(40.5,36.1) ; U3.26 34.975,22.4 v1(37.8,22.4) ; RC8.4 37.43,28.77 v1(37.8,28.4) 38.74,27.46 I2C_CONN.1 54.04,27.5 v1(56,27.5) 56.04,27.46 J7.1 ; U2.6 v1(40.465,32.065) ; v1(53.6,39) v1(56,39) ; v1(56,12.3) 65.38,12.3 LCD_CONN.1
  Bottom Layer w0.254: J16.8 17.24,20.04 18.1,20.9 21.1,20.9 21.9,20.1 21.9,12.3 23.2,11 36.5,11 37.8,12.3 v1(37.8,22.4) v1(37.8,28.4) ; v1(29.7,36.1) v1(29.7,41.1) ; v1(40.465,27.435) v1(40.465,32.065) v1@40.465,36.1 ; v1(53.6,39) 53.6,46.22 J21_JETSON_CONNECTOR.5 ; v1(56,12.3) v1(56,27.5) v1(56,39)
SDA: I2C_CONN.2 J7.2 J16.7 J21_JETSON_CONNECTOR.3 LCD_CONN.2 RC2.2 RC8.3 U1.15 U2.5 U3.27 | length 149.7
  Top Layer w0.254: U1.15 v1(27.675,38.675) 28.745,39.745 RC2.2 ; v1(27.7,35.5) v1(36.4,35.5) ; U3.27 v1(36.475,23.075) ; RC8.3 v1(36.5,27.9) ; v1(36.505,30.795) U2.5 41.705,30.795 42.5,30 I2C_CONN.2 v1(56.9,30) J7.2 ; v1(56.9,17.8) 65.66,17.8 LCD_CONN.2
  Bottom Layer w0.254: J16.7 15.8,14.98 15.8,21 16.7,21.9 21.8,21.9 22.8,20.9 22.8,12.6 23.5,11.9 35.3,11.9 36.475,13.075 v1(36.475,23.075) 36.475,27.875 v1(36.5,27.9) ; v1(27.675,38.675) 27.675,35.525 v1(27.7,35.5) ; v1(36.4,35.5) 36.4,30.9 v1@36.5,30.8 ; v1@36.5,23 v1(36.5,27.9) ; v1(36.505,30.795) v1@36.5,30.8 ; v1(56.9,17.8) v1(56.9,30) 56.9,44.087 56.419,44.569 56.419,46.499 J21_JETSON_CONNECTOR.3 ; v1(36.5,27.9) v1@36.5,30.8
SQW: RC2.4 U1.3 | length 33
  Top Layer w0.254: U1.3 20.495,37.405 v1(20.5,37.4) ; v1(20.5,42.3) v1(34.5,42.3) ; RC2.4 29.7,37.688 30.1,37.288 33.988,37.288 v1(34.5,37.3)
  Bottom Layer w0.254: v1(20.5,37.4) v1(20.5,42.3) ; v1(34.5,37.3) v1(34.5,42.3)
TXD0: J21_JETSON_CONNECTOR.8 UART_CONN.1 | length 35
  Top Layer w0.254: v1(52.38,38.02) 52.4,38 v1(69,38)
  Bottom Layer w0.254: v1(52.38,38.02) J21_JETSON_CONNECTOR.8 ; UART_CONN.1 69,29.46 v1(69,38)
V+: J10.2 J11.2 J12.2 J17.2 J18.2 J19.2 J20.2 J21.2 J22.2 J23.2 | length 22.5
  Top Layer w1.016: J17.2 J18.2 J19.2 J20.2 J21.2 J22.2 J23.2 J10.2 J11.2 J12.2
pads on no net: J16.1 J16.2 J16.3 J16.4 J21_JETSON_CONNECTOR.11 J21_JETSON_CONNECTOR.13 J21_JETSON_CONNECTOR.15 J21_JETSON_CONNECTOR.16 J21_JETSON_CONNECTOR.19 J21_JETSON_CONNECTOR.21 J21_JETSON_CONNECTOR.22 J21_JETSON_CONNECTOR.23 J21_JETSON_CONNECTOR.24 J21_JETSON_CONNECTOR.26 J21_JETSON_CONNECTOR.27 J21_JETSON_CONNECTOR.28 J21_JETSON_CONNECTOR.31 J21_JETSON_CONNECTOR.32 J21_JETSON_CONNECTOR.33 J21_JETSON_CONNECTOR.36 J21_JETSON_CONNECTOR.37 RC1.1 RC5.3 RC5.4 RC5.5 RC5.6 U1.4 U1.5 U1.6 U1.7 U1.8 U1.9 U1.10 U1.11 U1.12 U3.17 U3.18 U3.19 U3.20 U3.21 U3.22

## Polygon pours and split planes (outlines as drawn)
GND on Top Layer "Top Layer-GND" (solid, remove dead copper, pour order 0): 0,0 70,0 70,50 0,50
GND on Bottom Layer "Bottom Layer-GND" (solid, remove dead copper, pour order 1): 0,0 70,0 70,50 0,50

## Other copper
Top Layer:
  region net +3V3_VDC: 30.8,40 63.7,40 63.7,46.6 63.7,49.6 38.8,49.6 38.8,46.8 40.6,46.8 40.6,48.6 59,48.6 59,46.6 62.5,46.6 62.5,41.2 30.8,41.2
  region net +3V3_VDC: 62.4,47.2
Bottom Layer:
  region: 61.8,49.6

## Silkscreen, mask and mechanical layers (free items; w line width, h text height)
Top Overlay:
  lines w0.127: 50.6,37.42 50.6,38.3 50.8,38.5 53,38.5 ; 60,38.5 62.7,38.5 62.85,38.35 62.85,37.42
  text "BT_1" at 1,49.4 h0.7 r270
  text "BT_2" at 1,41.5 h0.7 r270
  text "GND" at 47.4,34.8 h0.7
  text "BT_3" at 1.1,33.5 h0.7 r270
  text "+3V3" at 47.2,32.2 h0.7
  text "SDA" at 47.4,29.6 h0.7
  text "SCL" at 47.4,27.2 h0.7
  text "BT_4" at 1,25.5 h0.7 r270
  text "LED" at 14,25 h0.7
  text "-" at 13.6,23.2 h0.7
  text "SENSOR_1" at 51,22.5 h0.7
  text "SENSOR_2" at 57.4,22.5 h0.7
  text "+" at 13.6,20.6 h0.7
  text "+5V" at 47.5,18.7 h0.7
  text "SCL" at 13,16 h0.7
  text "GND" at 47.5,16 h0.7
  text "IO" at 47.9,13.5 h0.7
  text "SDA" at 13,13 h0.7
  text "+3V3" at 12.2,10.6 h0.7
  text "GND" at 13,8 h0.7
  text "MPU-9250" at 5.5,7.5 h0.8
  text "PWM" at 21.1,6.6 h0.7
  text "V+" at 21.1,4 h0.7
  text "Design by FPT" at 51.5,2.5 h0.8
  text "GND" at 20.9,1.5 h0.7
  text "version 1.0.2" at 51.5,0.5 h0.8
Drill Drawing:
  the board outline again, w0.254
